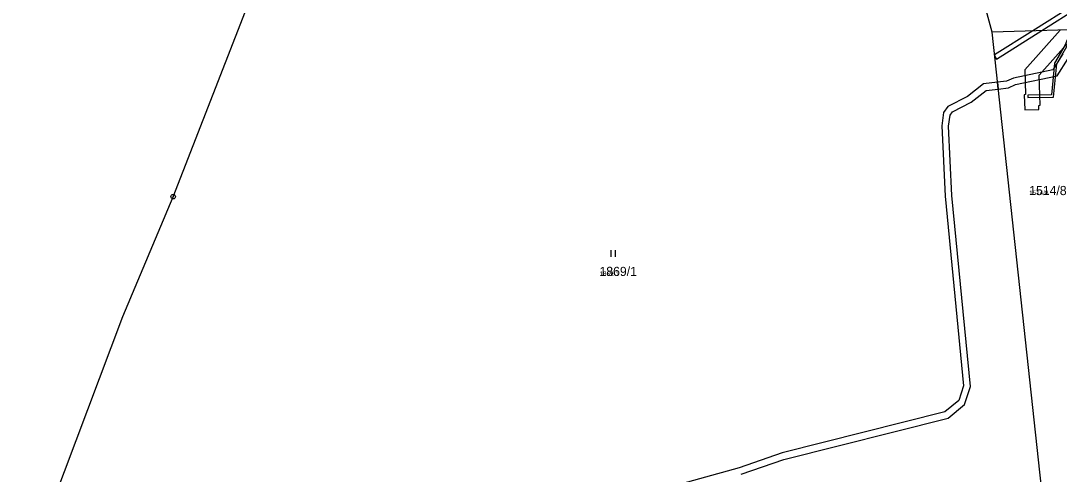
# Model space of a CAD drawing. Extents: x -763628 to -761565, y -976033 to -973833.
# Drawn here: x -763618.7 to -763391.9, y -975317.9 to -975218.9 of the extents above; entities that cross this region are included whole.
import ezdxf

# ---------------------------------------------------------------- set-up
doc = ezdxf.new("R2010")
doc.units = 0
for name, color, linetype in [('KN_cisla parcel 1000', 7, 'Continuous'), ('KN_cisla parcel 500', 7, 'Continuous'), ('KN_hranice parcel', 7, 'Continuous'), ('KN_hranice uzemi', 7, 'Continuous'), ('KN_vecna bremena', 7, 'Continuous'), ('KN_znacky bodu BP', 7, 'Continuous'), ('KN_znacky kultur', 7, 'Continuous')]:
    doc.layers.add(name, color=color, linetype=linetype)

msp = doc.modelspace()

# ---------------------------------------------------------------- linework, layer by layer
at = {"layer": 'KN_hranice parcel'}
for p, q in [((-763406.54, -975221.39), (-763408.27, -975215.01)), ((-763395.74, -975320.8), (-763406.54, -975221.39))]:
    msp.add_line(p, q, dxfattribs=at)
msp.add_lwpolyline([(-763376.33, -975220.79), (-763382.58, -975220.62), (-763406.54, -975221.39)], dxfattribs=at)
at = {"layer": 'KN_hranice uzemi'}
msp.add_lwpolyline([(-763618.69, -975360.14), (-763611.7, -975324.07), (-763596.41, -975283.44), (-763585.4, -975257.3), (-763565.26, -975205.55), (-763549.6, -975152.17), (-763547.37, -975144.54), (-763536.09, -975107.4)], dxfattribs=at)
at = {"layer": 'KN_vecna bremena'}
for points in [[(-763406, -975226.32), (-763405.97, -975226.66), (-763405.6, -975227.25), (-763395.69, -975221.04), (-763387.57, -975215.95), (-763353.39, -975221.41), (-763335.82, -975221.89), (-763292.21, -975223.16), (-763267.58, -975224.77), (-763284.3, -975223.39), (-763316.29, -975221.68), (-763353.29, -975220.4), (-763382.81, -975215.71), (-763388.81, -975215.55), (-763397.68, -975221.11)], [(-763386.32, -975215.61), (-763386.86, -975215.6), (-763389.17, -975220.83), (-763390.69, -975224.28), (-763392.91, -975228.17), (-763393.6, -975235.08), (-763398.75, -975235.15), (-763398.74, -975235.65), (-763393.15, -975235.58), (-763392.43, -975228.33), (-763390.25, -975224.51), (-763388.62, -975220.81)], [(-763396.32, -975238.24), (-763396.35, -975237.42), (-763396.06, -975237.34), (-763396.23, -975230.77), (-763388.54, -975222.08), (-763387.05, -975220.84), (-763386.85, -975220.76), (-763391.65, -975220.91), (-763399.37, -975229.63), (-763399.22, -975234.96), (-763399.55, -975235.04), (-763399.42, -975238.36)]]:
    msp.add_lwpolyline(points, close=True, dxfattribs=at)
for points in [[(-763391.1, -975226.1), (-763393.28, -975229.6), (-763401.87, -975231.39), (-763403.38, -975232.09), (-763405.35, -975232.32), (-763405.19, -975233.81), (-763402.96, -975233.55), (-763401.41, -975232.83), (-763392.34, -975230.94), (-763389.96, -975227.1)], [(-763461.38, -975317.89), (-763452, -975314.67), (-763416.15, -975305.61), (-763412.56, -975302.64), (-763411.27, -975298.73), (-763415.32, -975257.07), (-763416.05, -975241.88), (-763415.7, -975239.5), (-763415.2, -975238.78), (-763411.08, -975236.69), (-763407.83, -975234.11), (-763405.19, -975233.81), (-763405.35, -975232.32), (-763408.41, -975232.67), (-763411.92, -975235.43), (-763416.2, -975237.62), (-763417.14, -975238.92), (-763417.55, -975241.8), (-763416.82, -975257.19), (-763412.79, -975298.57), (-763413.84, -975301.76), (-763416.85, -975304.23), (-763452.42, -975313.23), (-763461.82, -975316.45), (-763506.44, -975328.83)]]:
    msp.add_lwpolyline(points, dxfattribs=at)
at = {"layer": 'KN_znacky bodu BP'}
for radius in [0.5, 0.0303]:
    msp.add_circle((-763585.4, -975257.3), radius, dxfattribs=at)
at = {"layer": 'KN_znacky kultur'}
for p, q in [((-763489.76, -975270.46), (-763489.76, -975268.96)), ((-763488.76, -975270.46), (-763488.76, -975268.96))]:
    msp.add_line(p, q, dxfattribs=at)

# ---------------------------------------------------------------- texts
at = {"layer": 'KN_cisla parcel 1000'}
for s, p in [('1514/8', (-763398.45, -975256.95)), ('1869/1', (-763492.3, -975274.61))]:
    msp.add_text(s, height=2, dxfattribs=at).set_placement(p)
at = {"layer": 'KN_cisla parcel 500'}
for s, p in [('1514/8', (-763398.45, -975256.95)), ('1869/1', (-763492.3, -975274.61))]:
    msp.add_text(s, height=1, dxfattribs=at).set_placement(p)

doc.saveas('drawing.dxf')
